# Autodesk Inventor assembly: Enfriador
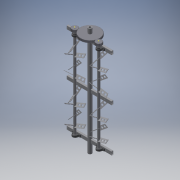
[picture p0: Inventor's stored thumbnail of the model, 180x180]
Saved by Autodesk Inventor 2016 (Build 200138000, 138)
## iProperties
Created: 2016-10
Part Number: Enfriador
Document SubType Name: Assembly
Designer: Ingenieria
Author: Ingenieria
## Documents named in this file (4)
- C:\Users\ingenieria\Desktop\Project\Enfriador.iam
- C:\Users\ingenieria\Desktop\Project\soporte_satelites.iam
- C:\Users\ingenieria\Desktop\Project\satelite_con_soporte.iam
- C:\Users\ingenieria\Desktop\Project\Enfriador\engranaje central.iam
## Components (4 placed, 3 different names)
1. soporte_satelites:1 [sub-assembly] — Mate:1, Angle:3, Mate:3, Mate:6, Tangent:1, Mate:8, Tangent:2
2. satelite_con_soporte:1 [sub-assembly] — Mate:6, Tangent:1, Mate:10, Rotation:2
3. satelite_con_soporte:2 [sub-assembly] — Mate:7, Mate:8, Tangent:2, Flush:1, Rotation:1
4. Spur Gears:1 [sub-assembly] — Mate:11, Flush:1, Rotation:1, Rotation:2
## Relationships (13: Mate 7, Tangent 2, RelateRotation 2, Angle 1, Flush 1)
- Mate:1: soporte_satelites:1
- Angle:3: soporte_satelites:1
- Mate:3: soporte_satelites:1
- Mate:6: soporte_satelites:1 ↔ satelite_con_soporte:1
- Tangent:1: soporte_satelites:1 ↔ satelite_con_soporte:1
- Mate:7: satelite_con_soporte:2
- Mate:8: soporte_satelites:1 ↔ satelite_con_soporte:2
- Tangent:2: soporte_satelites:1 ↔ satelite_con_soporte:2
- Mate:10: satelite_con_soporte:1
- Mate:11: Spur Gears:1
- Flush:1: satelite_con_soporte:2 ↔ Spur Gears:1
- Rotation:1 [RelateRotation]: satelite_con_soporte:2 ↔ Spur Gears:1
- Rotation:2 [RelateRotation]: satelite_con_soporte:1 ↔ Spur Gears:1
